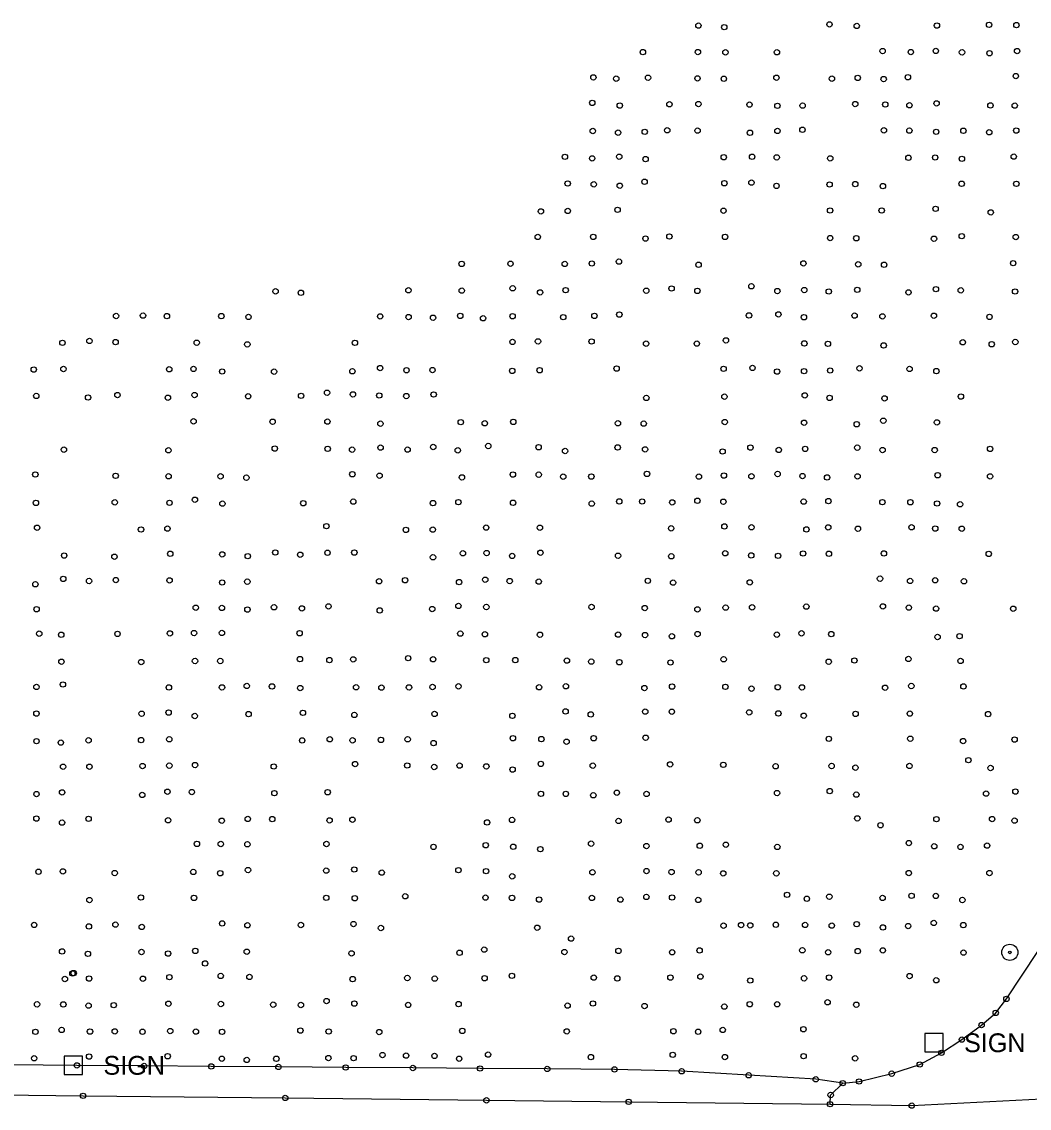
# Model space of a CAD drawing. Extents: x 20503438 to 20508873, y 7964251 to 7984667.
# Drawn here: x 20505708 to 20506082.7, y 7970567.6 to 7970971.8 of the extents above; entities that cross this region are included whole.
import ezdxf

# ---------------------------------------------------------------- set-up
doc = ezdxf.new("R2010")
doc.units = 0
for name, color, linetype in [('SurConcreteSlab', 7, 'Continuous'), ('SurEdgeRoadPaved', 7, 'Continuous'), ('SurEdgeShoulderUnpaved', 7, 'Continuous'), ('SurPointsNonDTM', 7, 'Continuous'), ('SurRoadPoints', 7, 'Continuous'), ('SurSurveyPoints', 7, 'Continuous')]:
    doc.layers.add(name, color=color, linetype=linetype)

msp = doc.modelspace()

# ---------------------------------------------------------------- linework, layer by layer
at = {"layer": 'SurConcreteSlab'}
msp.add_lwpolyline([(20506008.62, 7970569.15), (20506038.99, 7970568.62), (20506092.16, 7970571.34), (20506112.99, 7970571.23), (20506134.91, 7970571.99), (20506155.87, 7970572.09)], dxfattribs=at)
at = {"layer": 'SurEdgeRoadPaved'}
msp.add_lwpolyline([(20505669.66, 7970572.93), (20505730.8, 7970572.24), (20505805.95, 7970571.47), (20505880.8, 7970570.58), (20505933.71, 7970570.02), (20506008.62, 7970569.15), (20506008.82, 7970572.55), (20506013.34, 7970576.96), (20506019.41, 7970577.58), (20506031.53, 7970580.5), (20506041.98, 7970583.9), (20506050.04, 7970588.24), (20506057.61, 7970593.17), (20506064.97, 7970598.56), (20506070.21, 7970603.1), (20506074.21, 7970608.31), (20506085.84, 7970625.99)], dxfattribs=at)
at = {"layer": 'SurEdgeShoulderUnpaved'}
msp.add_lwpolyline([(20506013.34, 7970576.96), (20506003.27, 7970578.4), (20505978.34, 7970579.89), (20505953.4, 7970581.38), (20505928.43, 7970582.06), (20505903.43, 7970582.24), (20505878.44, 7970582.42), (20505853.45, 7970582.6), (20505828.45, 7970582.79), (20505803.45, 7970582.99), (20505778.46, 7970583.18), (20505753.46, 7970583.38), (20505728.47, 7970583.57), (20505703.47, 7970583.73), (20505678.47, 7970583.86), (20505653.47, 7970583.99), (20505628.47, 7970584.12), (20505603.48, 7970584.03), (20505578.48, 7970583.43), (20505553.53, 7970582.26), (20505528.79, 7970578.89), (20505515.58, 7970576.01)], dxfattribs=at)
at = {"layer": 'SurPointsNonDTM'}
for centre in [(20506060.05, 7970697.11), (20506027.36, 7970672.91), (20505992.64, 7970647.02), (20505975.52, 7970635.76), (20505912.27, 7970630.73), (20505830.63, 7970625.24), (20505776.14, 7970621.49), (20505726.82, 7970617.77), (20505727.28, 7970617.9)]:
    msp.add_circle(centre, 1, dxfattribs=at)
at = {"layer": 'SurRoadPoints'}
for points in [[(20506047.23, 7970588.56), (20506047.23, 7970588.56), (20506050.66, 7970588.56), (20506050.66, 7970595.42), (20506043.8, 7970595.42), (20506043.8, 7970588.56), (20506047.23, 7970588.56)], [(20505727.14, 7970580.16), (20505727.14, 7970580.16), (20505730.57, 7970580.16), (20505730.57, 7970587.02), (20505723.71, 7970587.02), (20505723.71, 7970580.16), (20505727.14, 7970580.16)]]:
    msp.add_lwpolyline(points, dxfattribs=at)
for radius in [3, 0.5]:
    msp.add_circle((20506075.46, 7970625.62), radius, dxfattribs=at)
at = {"layer": 'SurSurveyPoints'}
for centre in [(20505959.64, 7970970.36), (20505969.26, 7970969.77), (20506008.4, 7970970.79), (20506018.53, 7970970.24), (20506048.35, 7970970.38), (20506067.73, 7970970.63), (20506077.91, 7970970.53), (20505938.98, 7970960.48), (20505959.46, 7970960.5), (20505969.7, 7970960.41), (20505988.85, 7970960.44), (20506028.16, 7970960.89), (20506038.64, 7970960.5), (20506047.94, 7970960.93), (20506057.68, 7970960.41), (20506067.91, 7970960.09), (20506078.18, 7970960.87), (20505920.57, 7970951.09), (20505929.07, 7970950.61), (20505940.9, 7970950.97), (20505959.3, 7970950.71), (20505969.09, 7970950.57), (20505988.64, 7970950.95), (20506009.28, 7970950.61), (20506018.89, 7970950.9), (20506028.54, 7970950.47), (20506037.54, 7970951.15), (20506077.7, 7970951.58), (20505920.16, 7970941.61), (20505930.39, 7970940.62), (20505948.86, 7970941.09), (20505959.63, 7970941.18), (20505978.64, 7970940.97), (20505989.01, 7970940.51), (20505998.4, 7970940.58), (20506017.98, 7970941.16), (20506029.15, 7970941), (20506038.12, 7970940.72), (20506048.22, 7970941.41), (20506068.26, 7970940.65), (20506077.3, 7970940.59), (20505998.34, 7970931.59), (20505920.36, 7970931.15), (20505929.78, 7970930.53), (20505939.68, 7970930.83), (20505948.04, 7970931.41), (20505959.33, 7970931.28), (20505978.81, 7970930.48), (20505989.04, 7970931.17), (20506028.62, 7970931.4), (20506038.1, 7970931.3), (20506048.07, 7970930.83), (20506058.18, 7970931.22), (20506067.8, 7970930.68), (20506077.86, 7970931.32), (20505909.99, 7970921.54), (20505920.13, 7970920.97), (20505930.19, 7970921.59), (20505940, 7970920.69), (20505969.06, 7970921.39), (20505979.62, 7970921.56), (20505988.76, 7970921.34), (20506008.67, 7970920.97), (20506037.74, 7970921.19), (20506047.69, 7970921.29), (20506057.63, 7970920.79), (20506076.92, 7970921.62), (20505911.01, 7970911.61), (20505920.71, 7970911.31), (20505939.61, 7970912.26), (20505969.29, 7970911.72), (20505979.36, 7970911.94), (20506017.97, 7970911.39), (20506057.55, 7970911.51), (20506077.89, 7970911.5), (20505930.38, 7970910.78), (20505988.68, 7970910.74), (20506008.43, 7970911.25), (20506028.24, 7970910.64), (20505901.06, 7970901.23), (20505911.05, 7970901.41), (20505929.56, 7970901.83), (20505968.97, 7970901.49), (20506008.62, 7970901.57), (20506027.8, 7970901.58), (20506047.86, 7970902.2), (20506068.36, 7970900.86), (20505899.89, 7970891.74), (20505920.51, 7970891.76), (20505939.96, 7970891.14), (20505948.84, 7970891.9), (20505969.54, 7970891.76), (20506008.65, 7970891.32), (20506018.36, 7970891.26), (20506047.26, 7970891.07), (20506057.57, 7970892.02), (20506077.68, 7970891.7), (20505871.59, 7970881.72), (20505889.74, 7970881.77), (20505909.93, 7970881.7), (20505919.99, 7970881.86), (20505930.09, 7970882.57), (20505959.68, 7970881.38), (20505998.69, 7970881.89), (20506019.07, 7970881.55), (20506028.71, 7970881.38), (20506076.7, 7970881.99), (20505802.36, 7970871.5), (20505811.79, 7970870.97), (20505851.79, 7970871.89), (20505871.61, 7970871.77), (20505890.56, 7970872.63), (20505900.75, 7970871.1), (20505910.26, 7970871.94), (20505940.26, 7970871.74), (20505949.64, 7970872.56), (20505959.25, 7970871.68), (20505979.33, 7970873.4), (20505989, 7970871.6), (20505999.02, 7970871.99), (20506008.13, 7970871.45), (20506018.71, 7970872.06), (20506037.77, 7970871.1), (20506047.97, 7970872.31), (20506057.21, 7970871.88), (20506077.41, 7970871.45), (20505930.23, 7970862.87), (20505989.39, 7970862.92), (20505743.05, 7970862.33), (20505753.07, 7970862.48), (20505761.95, 7970862.28), (20505782.19, 7970862.29), (20505792.31, 7970861.99), (20505841.28, 7970862.17), (20505851.84, 7970861.93), (20505860.94, 7970861.69), (20505871.04, 7970862.38), (20505879.55, 7970861.49), (20505890.53, 7970862.25), (20505909.35, 7970861.89), (20505920.96, 7970862.38), (20505978.45, 7970862.54), (20505998.9, 7970861.88), (20506017.73, 7970862.48), (20506028.07, 7970862.19), (20506047.23, 7970862.43), (20506067.9, 7970862.01), (20505723.11, 7970852.35), (20505733.14, 7970853.04), (20505742.87, 7970852.61), (20505773.04, 7970852.4), (20505791.86, 7970851.78), (20505831.9, 7970852.34), (20505890.5, 7970852.68), (20505899.98, 7970852.89), (20505919.9, 7970852.85), (20505940.19, 7970852.04), (20505959.05, 7970852.06), (20505969.89, 7970853.25), (20505999.04, 7970852.11), (20506007.82, 7970851.98), (20506028.54, 7970851.38), (20506057.96, 7970852.56), (20506068.72, 7970851.83), (20506077.51, 7970852.66), (20505723.47, 7970842.62), (20505771.85, 7970842.64), (20505841.25, 7970842.96), (20505929.22, 7970842.79), (20505969, 7970842.68), (20505979.76, 7970843.02), (20506019.55, 7970842.87), (20506038.18, 7970842.63), (20505712.43, 7970842.42), (20505762.82, 7970842.51), (20505782.51, 7970841.68), (20505801.81, 7970841.63), (20505830.93, 7970841.77), (20505851.07, 7970842.16), (20505860.73, 7970842.21), (20505890.39, 7970841.92), (20505900.58, 7970842.16), (20505988.89, 7970841.67), (20505998.94, 7970841.81), (20506008.65, 7970842.06), (20506048.14, 7970841.83), (20505713.38, 7970832.59), (20505732.62, 7970832.01), (20505743.57, 7970832.92), (20505762.32, 7970831.93), (20505772.25, 7970832.93), (20505792.18, 7970832.47), (20505811.85, 7970832.63), (20505821.51, 7970833.8), (20505831.16, 7970833.16), (20505840.93, 7970832.75), (20505851, 7970832.55), (20505861.17, 7970833.13), (20505940.27, 7970831.86), (20505969.31, 7970832.33), (20505999.2, 7970832.8), (20506008.43, 7970831.88), (20506028.87, 7970831.68), (20506057.27, 7970832.37), (20505771.86, 7970823.15), (20505801.28, 7970822.99), (20505821.64, 7970823.05), (20505871.25, 7970822.84), (20505880.18, 7970822.44), (20505890.79, 7970822.94), (20505929.7, 7970822.42), (20505969.44, 7970822.89), (20505998.94, 7970822.63), (20506028.41, 7970823.38), (20506048.35, 7970822.76), (20505841.37, 7970822.28), (20505939.29, 7970822.3), (20506018.51, 7970822.07), (20505723.63, 7970812.61), (20505762.51, 7970812.37), (20505802.08, 7970813.03), (20505821.75, 7970812.92), (20505830.82, 7970812.61), (20505841.42, 7970813.38), (20505851.47, 7970812.64), (20505861, 7970813.6), (20505870.14, 7970812.36), (20505881.49, 7970813.98), (20505900.21, 7970813.52), (20505910.04, 7970812.11), (20505929.6, 7970813.43), (20505939.8, 7970812.72), (20505968.64, 7970811.93), (20505978.99, 7970813.39), (20505989.53, 7970812.52), (20505999.34, 7970812.9), (20506018.73, 7970813.35), (20506028.14, 7970812.47), (20506047.51, 7970812.45), (20506068.12, 7970812.9), (20505713.01, 7970803.37), (20505742.89, 7970802.87), (20505762.59, 7970802.72), (20505781.91, 7970802.69), (20505791.51, 7970802.2), (20505830.92, 7970803.47), (20505841.05, 7970802.92), (20505871.7, 7970802.29), (20505890.63, 7970803.36), (20505900.24, 7970803.31), (20505909.35, 7970802.56), (20505919.82, 7970802.61), (20505940.51, 7970803.61), (20505959.82, 7970802.58), (20505969.13, 7970802.98), (20505979.37, 7970802.7), (20505989.1, 7970803.55), (20505998.36, 7970802.79), (20506007.49, 7970802.28), (20506018.82, 7970802.68), (20506048.63, 7970803.11), (20506068.11, 7970802.68), (20505713.25, 7970792.81), (20505742.55, 7970793.02), (20505762.92, 7970792.83), (20505772.37, 7970793.99), (20505782.6, 7970792.53), (20505812.66, 7970792.69), (20505831.28, 7970793.29), (20505860.92, 7970792.73), (20505870.36, 7970793.08), (20505890.69, 7970792.84), (20505919.95, 7970792.53), (20505930.21, 7970793.34), (20505938.72, 7970793.33), (20505949.91, 7970793), (20505959.26, 7970793.6), (20505968.92, 7970793.23), (20505998.78, 7970793.3), (20506007.99, 7970793.46), (20506028.06, 7970793.08), (20506038.47, 7970793.06), (20506048.43, 7970792.59), (20506056.96, 7970792.29), (20505713.69, 7970783.56), (20505752.32, 7970782.91), (20505762.15, 7970783.24), (20505821.27, 7970784.15), (20505850.84, 7970782.77), (20505860.85, 7970782.86), (20505880.7, 7970783.63), (20505900.68, 7970783.58), (20505949.5, 7970783.34), (20505969.3, 7970784.04), (20505979.38, 7970783.73), (20505999.81, 7970782.93), (20506007.91, 7970783.7), (20506018.98, 7970783.19), (20506038.91, 7970783.74), (20506047.72, 7970783.27), (20506057.59, 7970783.2), (20505763.2, 7970773.87), (20505802.27, 7970774.35), (20505821.68, 7970774.25), (20505831.67, 7970774.34), (20505872.05, 7970774.06), (20505880.87, 7970774.16), (20505900.87, 7970774.27), (20505969.6, 7970774.08), (20505998.59, 7970773.99), (20506008.19, 7970773.87), (20506028.63, 7970774), (20506067.63, 7970773.85), (20505723.75, 7970773.22), (20505742.44, 7970772.78), (20505782.55, 7970773.64), (20505792.04, 7970773), (20505811.53, 7970773.52), (20505860.92, 7970772.57), (20505890.37, 7970773.09), (20505929.74, 7970773.17), (20505949.55, 7970772.96), (20505979.27, 7970773.26), (20505989.27, 7970773.11), (20505713.03, 7970762.55), (20505723.41, 7970764.54), (20505732.99, 7970763.75), (20505742.96, 7970764.09), (20505762.93, 7970763.98), (20505782.51, 7970763.19), (20505791.86, 7970763.51), (20505840.88, 7970763.66), (20505850.54, 7970764.05), (20505870.62, 7970763.34), (20505880.36, 7970764.24), (20505889.44, 7970763.73), (20505900.26, 7970763.53), (20505940.82, 7970763.82), (20505950.21, 7970763.15), (20505978.75, 7970763.24), (20506027.18, 7970764.63), (20506038.36, 7970763.77), (20506047.7, 7970764.03), (20506058.41, 7970763.64), (20505772.7, 7970753.82), (20505782.41, 7970753.73), (20505801.79, 7970753.99), (20505822.06, 7970754.32), (20505870.37, 7970754.48), (20505880.76, 7970754.09), (20505919.89, 7970754.08), (20505939.67, 7970753.69), (20505969.77, 7970753.85), (20505979.61, 7970753.96), (20505999.77, 7970754.23), (20506028.25, 7970754.3), (20506037.9, 7970753.85), (20505713.48, 7970753.26), (20505791.91, 7970753.13), (20505812.16, 7970753.57), (20505841.1, 7970752.8), (20505860.63, 7970753.33), (20505959.28, 7970753.2), (20506048.04, 7970753.5), (20506076.73, 7970753.43), (20505714.46, 7970744.16), (20505722.64, 7970743.74), (20505743.58, 7970744.09), (20505763.08, 7970744.27), (20505772.04, 7970744.4), (20505782.41, 7970744.42), (20505811.32, 7970744.33), (20505871.09, 7970744.19), (20505880.22, 7970743.94), (20505900.71, 7970743.77), (20505929.77, 7970743.81), (20505939.79, 7970743.64), (20505949.79, 7970743.2), (20505959.31, 7970744.01), (20505988.8, 7970743.79), (20505997.98, 7970744.29), (20506009.04, 7970744), (20506048.59, 7970742.92), (20506056.76, 7970743.24), (20505722.71, 7970733.72), (20505752.4, 7970733.61), (20505772.41, 7970733.99), (20505781.81, 7970733.99), (20505811.44, 7970734.69), (20505822.39, 7970734.32), (20505831.26, 7970734.6), (20505851.68, 7970735.05), (20505860.97, 7970734.64), (20505880.74, 7970734.31), (20505891.53, 7970734.33), (20505910.72, 7970734.15), (20505919.8, 7970733.76), (20505930.23, 7970733.55), (20505969.03, 7970734.63), (20506008.1, 7970733.73), (20506017.66, 7970734.19), (20506037.74, 7970734.75), (20506057.14, 7970734.03), (20505949.25, 7970733.43), (20505713.44, 7970724.34), (20505723.28, 7970725.25), (20505762.69, 7970724.15), (20505782.44, 7970724.18), (20505791.64, 7970724.71), (20505801.05, 7970724.53), (20505811.54, 7970723.94), (20505832.31, 7970724.21), (20505841.75, 7970724.1), (20505852, 7970724.18), (20505860.75, 7970724.32), (20505870.4, 7970724.58), (20505900.37, 7970724.23), (20505910.36, 7970724.6), (20505939.55, 7970723.93), (20505949.83, 7970724.5), (20505969.66, 7970724.39), (20505979.39, 7970723.71), (20505989.14, 7970724.25), (20505998.15, 7970724.17), (20506029.07, 7970724.04), (20506038.83, 7970724.7), (20506058.21, 7970724.52), (20505713.43, 7970714.45), (20505752.55, 7970714.39), (20505762.6, 7970714.82), (20505772.3, 7970713.54), (20505792.33, 7970714.23), (20505812.56, 7970714.72), (20505831.68, 7970713.94), (20505861.5, 7970714.31), (20505890.44, 7970713.6), (20505910.22, 7970715.23), (20505919.61, 7970714.11), (20505939.85, 7970715.16), (20505949.75, 7970715.12), (20505978.55, 7970714.89), (20505989.37, 7970714.49), (20505998.82, 7970713.63), (20506018.1, 7970714.32), (20506038.27, 7970714.44), (20506067.37, 7970714.23), (20505890.63, 7970705.28), (20505920.68, 7970705.27), (20505940.02, 7970705.46), (20505713.45, 7970704.17), (20505722.5, 7970703.64), (20505732.82, 7970704.49), (20505752.36, 7970704.56), (20505762.84, 7970704.87), (20505812.27, 7970704.44), (20505822.54, 7970704.88), (20505831.02, 7970704.48), (20505841.57, 7970704.66), (20505851.5, 7970704.87), (20505861.12, 7970703.45), (20505901.23, 7970704.94), (20505910.59, 7970703.98), (20506008.15, 7970705.04), (20506038.45, 7970705.09), (20506058.1, 7970704.22), (20506077.24, 7970704.78), (20505723.33, 7970694.68), (20505733.14, 7970694.66), (20505752.89, 7970694.93), (20505762.85, 7970695.06), (20505772.42, 7970695.28), (20505801.68, 7970694.76), (20505831.96, 7970695.66), (20505851.34, 7970695.13), (20505861.39, 7970694.56), (20505870.81, 7970695.09), (20505880.76, 7970694.78), (20505890.52, 7970693.62), (20505901.03, 7970695.72), (20505920.33, 7970695.06), (20505949.1, 7970695.53), (20505968.9, 7970695.38), (20505988.36, 7970694.84), (20506009.19, 7970694.94), (20506018.02, 7970694.32), (20506038.14, 7970694.95), (20506068.31, 7970694.2), (20505722.98, 7970685.11), (20505762.15, 7970685.37), (20505771.23, 7970685.25), (20505821.74, 7970685.18), (20505929.3, 7970685), (20506008.48, 7970685.59), (20506077.53, 7970685.43), (20505713.46, 7970684.49), (20505752.77, 7970684.18), (20505801.92, 7970684.84), (20505901.08, 7970684.58), (20505910.32, 7970684.57), (20505920.55, 7970684.06), (20505940.34, 7970684.54), (20505988.88, 7970684.88), (20506018.37, 7970684.3), (20506066.65, 7970684.66), (20505713.42, 7970675.4), (20505722.95, 7970673.89), (20505732.83, 7970675.29), (20505762.4, 7970674.74), (20505782.35, 7970674.58), (20505792.03, 7970675.25), (20505801.14, 7970675.17), (20505822.46, 7970674.7), (20505830.96, 7970674.95), (20505881.04, 7970673.93), (20505890.32, 7970674.87), (20505929.96, 7970674.49), (20505948.53, 7970675), (20505959.24, 7970674.76), (20506018.74, 7970675.45), (20506048.18, 7970675.16), (20506068.87, 7970675.19), (20506077.23, 7970674.62), (20505773.13, 7970665.97), (20505782, 7970665.92), (20505791.88, 7970665.81), (20505821.3, 7970665.92), (20505861.11, 7970664.85), (20505880.54, 7970665.48), (20505890.75, 7970664.88), (20505919.71, 7970666.04), (20505940.3, 7970665.17), (20505960.15, 7970665.26), (20505969.84, 7970665.66), (20505988.99, 7970664.84), (20506037.9, 7970666.26), (20506047.36, 7970665.08), (20506057.12, 7970664.84), (20506067.02, 7970665.33), (20505900.85, 7970664), (20505714.19, 7970655.58), (20505723.26, 7970655.74), (20505742.54, 7970655.12), (20505771.77, 7970655.54), (20505781.78, 7970655.05), (20505792.12, 7970656.24), (20505821.22, 7970656.02), (20505831.64, 7970656.43), (20505841.86, 7970655.28), (20505870.39, 7970656.19), (20505880.66, 7970655.81), (20505890.41, 7970653.9), (20505920.22, 7970655.4), (20505940.33, 7970655.86), (20505949.65, 7970655.5), (20505959.72, 7970655.39), (20505968.88, 7970654.98), (20505988.62, 7970655.01), (20506037.88, 7970655.11), (20506067.88, 7970655.12), (20505733.13, 7970645.08), (20505752.31, 7970646.02), (20505772.03, 7970645.88), (20505821.23, 7970645.9), (20505831.83, 7970645.76), (20505850.6, 7970646.49), (20505880.45, 7970645.99), (20505890.31, 7970645.89), (20505900.37, 7970645.27), (20505920.02, 7970645.87), (20505930.62, 7970645.24), (20505940.28, 7970646.24), (20505949.86, 7970646.03), (20505959.59, 7970645.12), (20505999.97, 7970645.55), (20506008.34, 7970646.32), (20506028.15, 7970645.86), (20506038.91, 7970646.65), (20506047.94, 7970646.6), (20506057.81, 7970645.1), (20506047.17, 7970636.55), (20505712.58, 7970635.82), (20505732.94, 7970635.26), (20505742.8, 7970635.93), (20505752.61, 7970635.07), (20505782.5, 7970636.37), (20505791.89, 7970635.69), (20505811.79, 7970635.79), (20505831.36, 7970636.15), (20505841.56, 7970634.67), (20505899.7, 7970634.78), (20505968.99, 7970635.54), (20505978.92, 7970635.64), (20505988.44, 7970635.87), (20505999.3, 7970635.83), (20506009.24, 7970635.58), (20506018.5, 7970636.1), (20506028.26, 7970634.88), (20506037.65, 7970635.41), (20506058.17, 7970635.74), (20505722.98, 7970625.96), (20505732.59, 7970625.06), (20505752.5, 7970625.75), (20505762.38, 7970625.17), (20505772.51, 7970626.17), (20505791.66, 7970625.86), (20505870.79, 7970625.45), (20505879.99, 7970626.63), (20505909.79, 7970625.74), (20505929.9, 7970626.16), (20505949.87, 7970625.65), (20505960.08, 7970626.33), (20505998.29, 7970626.38), (20506007.9, 7970625.64), (20506018.92, 7970626.07), (20506028.23, 7970626.35), (20506058.24, 7970625.51), (20505762.89, 7970616.39), (20505781.96, 7970616.85), (20505792.65, 7970616.47), (20505890.26, 7970616.89), (20505920.72, 7970616.23), (20505949.24, 7970616.24), (20505960.4, 7970616.61), (20506008.26, 7970616.25), (20506038.18, 7970616.8), (20505724, 7970615.71), (20505733.02, 7970615.87), (20505753.02, 7970615.8), (20505831.04, 7970615.66), (20505851.38, 7970616.08), (20505861.56, 7970615.84), (20505880.12, 7970616), (20505929.47, 7970615.91), (20505978.93, 7970615.15), (20505998.92, 7970615.95), (20506048.11, 7970615.24), (20506074.21, 7970608.31), (20505713.65, 7970606.29), (20505723.43, 7970606.24), (20505732.82, 7970605.8), (20505742.18, 7970605.98), (20505762.51, 7970606.5), (20505782.05, 7970606.4), (20505801.51, 7970606.16), (20505811.78, 7970606.03), (20505821.33, 7970607.49), (20505831.68, 7970606.57), (20505851.69, 7970606.06), (20505870.45, 7970606.36), (20505910.98, 7970605.82), (20505920.39, 7970606.6), (20505939.61, 7970605.65), (20505969.28, 7970605.44), (20505978.72, 7970606.33), (20505988.93, 7970606.3), (20506007.66, 7970607.05), (20506018.36, 7970606.13), (20506070.21, 7970603.1), (20505713.07, 7970596.06), (20505722.8, 7970596.77), (20505733.35, 7970596.16), (20505742.57, 7970596.21), (20505752.88, 7970596.07), (20505763.2, 7970596.35), (20505772.73, 7970596.15), (20505782.46, 7970596.06), (20505811.6, 7970596.53), (20505822.12, 7970596.18), (20505871.82, 7970596.41), (20505910.66, 7970596.21), (20505950.35, 7970596.28), (20505959.55, 7970596.07), (20505968.68, 7970596.77), (20505998.7, 7970597.02), (20506064.97, 7970598.56), (20505840.94, 7970595.96), (20506057.61, 7970593.17), (20506050.04, 7970588.24), (20505712.59, 7970586.21), (20505733.01, 7970586.86), (20505762.23, 7970586.99), (20505782.38, 7970586.05), (20505791.65, 7970585.6), (20505802.66, 7970586.02), (20505822.03, 7970586.3), (20505831.39, 7970586.25), (20505842.14, 7970587.42), (20505850.92, 7970587.21), (20505861.48, 7970587.1), (20505870.66, 7970586.04), (20505881.4, 7970587.59), (20505919.64, 7970586.64), (20505950.09, 7970587.5), (20505969.48, 7970586.67), (20505998.76, 7970587), (20506017.91, 7970586.19), (20506041.98, 7970583.9), (20505728.47, 7970583.57), (20505753.46, 7970583.38), (20505778.46, 7970583.18), (20505803.45, 7970582.99), (20505828.45, 7970582.79), (20505853.45, 7970582.6), (20505878.44, 7970582.42), (20505903.43, 7970582.24), (20505928.43, 7970582.06), (20505953.4, 7970581.38), (20505978.34, 7970579.89), (20506031.53, 7970580.5), (20506003.27, 7970578.4), (20506013.34, 7970576.96), (20506019.41, 7970577.58), (20505730.8, 7970572.24), (20506008.82, 7970572.55), (20505805.95, 7970571.47), (20505880.8, 7970570.58), (20505933.71, 7970570.02), (20506008.62, 7970569.15), (20506008.62, 7970569.15), (20506038.99, 7970568.62)]:
    msp.add_circle(centre, 1, dxfattribs=at)

# ---------------------------------------------------------------- texts
at = {"layer": 'SurRoadPoints'}
for p in [(20506058.44, 7970588.49), (20505738.35, 7970580.09)]:
    msp.add_text('SIGN', height=6.995, rotation=360, dxfattribs=at).set_placement(p)

doc.saveas('drawing.dxf')
